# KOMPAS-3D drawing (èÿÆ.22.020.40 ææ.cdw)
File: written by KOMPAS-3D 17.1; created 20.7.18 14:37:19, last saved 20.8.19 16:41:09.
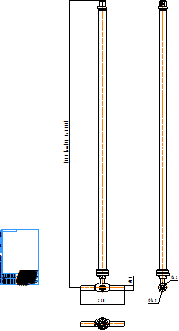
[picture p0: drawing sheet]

Sheet 1: A4, portrait

Title block, sheet 1: name: КШТ.22.020.40 С/С; sheets: 1; sheet format: A4; stored path: C:\Users\kka\KOMPAS_Work\Модели кранов для исследований\DN32\С удлинением\КШТ.22.032.40 СС.cdw

Referenced files in C:\Users\kka\KOMPAS_Work\Модели кранов для исследований\DN20\: АПТА.0203-1057.04.01 _ Корпус крана Ду20.m3d, АПТА.0203-2607.00.01 _ Шар Ду20.m3d, АПТА.0203-2607.02.02 _ Кольцо горловое Ду20.m3d, АПТА.0203-2607.02.03 _ Пружина тарельчатая Ду20.m3d, АПТА.0203-2607.02.04 _ Кольцо опорное Ду20.m3d, АПТА.0203-2607.02.05 _ Уплотнение седловое Ду20.m3d, АПТА.0203-2607.04.03 _ Шток Ду20 исполнение 1.m3d, АПТА.0203-1018.04.02 _ Корпус штока Ду10-32.m3d, АПТА.0203-1018.04.04 _ Шайба фрикционная Ду10-32.m3d, АПТА.0203-1057.03.01 _ Патрубок сварной точенный Ду20 (труба по ГОСТ).m3d, АПТА.0203-1057.00.00 _ Кран шаровой сварной Ду20 (Труба по ГОСТ).a3d!АПТА.0203-1057.00.00!Деталь (локальная).m3d, АПТА.0203-1057.00.00 _ Кран шаровой сварной Ду20 (Труба по ГОСТ).a3d!АПТА.0203-1057.00.00!Деталь (локальная) 1.m3d, Кольцо Viton 10.3x2.4.m3d, Кольцо EPDM 10.3x2.4.m3d, АПТА.0203-1018.01.02 _ Подкладка для кольца Ду10-32.m3d, АПТА.0203-1018.01.01 _ Кольцо прокладочное Ду10-32.m3d, АПТА.0203-1057.00.00 _ Кран шаровой сварной Ду20 (Труба по ГОСТ).a3d
Referenced files in C:\Program Files\ASCON\KOMPAS-3D v17\Libs\PartLib\DATA\VAULT\methods\kompas\3d\: PLib_Pin_3128_712.m3d, PLib_Blind_Nut_type1_900.m3d, PLib_Bolt_1_900.m3d, PLib_Washer_2_712.m3d, PLib_Pins_GOST_14229_911.m3d, PLib_Screw_GOST_8878-84_900.m3d
Referenced files in C:\Users\kka\KOMPAS_Work\Модели кранов для исследований\DN32\: ручка15-32.m3d, АПТА.0203-1018.03.00 _ Ручка Ду10-32.a3d
Referenced files in C:\Users\kka\KOMPAS_Work\КШ удлиненные ПП МОСФЛОУЛАЙН ф. ADL\DN25ПП\: ухватка15-32.m3d
Referenced files in C:\Users\kka\KOMPAS_Work\Удлинения БИВАЛ ф. ADL\Небюджет\Специальные ISO фланцы\: Фланец Ду15-32.m3d
Referenced files in C:\Users\kka\KOMPAS_Work\Удлинения БИВАЛ ф. ADL\Небюджет\Удлинения_2010\УШДн15-32\: УШ.251.00.03 _ Фланец нижний.m3d, УШ.251.00.07 _ Прокладка Ду20-50.m3d, УШ.251.00.05 _ Шток удлинителя Ду20-50.m3d, УШ.251.00.04 _ Гайка 32.m3d, УШ.251.00.01 _ Крышка удлинения.m3d, УШ.251.00.06 _ Тело удлинителя Ду20-50.m3d, УШ.251.00.08 _ Адаптер Ду20-32.m3d, УШ.251.00.00 _ Удлинение штока Ду20-32.a3d!УШ.251.00.00!Деталь (локальная).m3d, АПТА.0203-2617.11.03 - Кольцо прокладочное Ду65-80.m3d, УШ.251.00.00 _ Удлинение штока Ду20-32.a3d!УШ.251.00.00!Деталь (локальная) 1.m3d, УШ.251.00.00 _ Удлинение штока Ду20-32.a3d
Referenced files in C:\Users\kka\KOMPAS_Work\Модели кранов для исследований\DN80\: Кольцо EPDM 19.2x3.m3d
Referenced files in C:\Users\kka\KOMPAS_Work\Модели кранов для исследований\DN20\С удлинением\: КШТ.22.020.40 СС.a3d
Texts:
  kka
  adl
  Рама для чертежей
  Лит-Масса-Масштаб
  Материал-Предприятие
  Масштаб
  Изм.
  Лист
  № докум.
  Подп.
  Дата
  Лит.
  Разраб.
  Пров.
  Т.контр.
  Листов
  Внимание! Данный продукт является объектом авторского права ООО «Торговый Дом АДЛ».
  Запрещается изменение, копирование, распространение
  (в том числе путем копирования на другие сайты и ресурсы в Интернете)
  или любое иное использование информации и объектов без предварительного
  согласия правообладателя (ООО «Торговый Дом АДЛ»).
  Н.контр.
  Утв.
  ООО "Торговый дом АДЛ"
  Изменение
  Номер документа
  Подпись
  Обозначение документа
  Наименование изделия
  Масса изделия по ГОСТ 2.109-73
  Порядковый номер листа
  Общее количество листов в документе
  Характер работы, выполненной лицом, подписавшим документ
  Наименование или индекс предприятия, выпускающего документ
  Инв. № подл.
  Подп. и дата
  Взам. инв. №
  Инв. № дубл.
  Инвентарный номер подлинника по ГОСТ 2.501-68
  Подпись принявшего подлинник в отдел технической документации
  Инвентарный номер подлинника, взамен которого выпущен данный подлинник
  Инвентарный номер дубликата по ГОСТ 2.502-68
  Подпись принявшего дубликат в отдел технической документации
  Справ. №
  Перв. примен.
  Обозначение документа, взамен или на основании которого выпущен данный документ
  Обозначение документа, в котором впервые записан данный документ
  Подпись лица, копировавшего чертеж
  Обозначение формата листа
  !Рама для чертежа
  Корпус крана Ду20
  АПТА.0203-1057.04.01
  Шар Ду20
  АПТА.0203-2607.00.01
  Кольцо горловое Ду20
  АПТА.0203-2607.02.02
  Пружина тарельчатая Ду20
  АПТА.0203-2607.02.03
  Кольцо опорное Ду20
  АПТА.0203-2607.02.04
  Уплотнение седловое Ду20
  АПТА.0203-2607.02.05
  Шток Ду20 исполнение 1
  АПТА.0203-2607.04.03
  Корпус штока Ду10-32
  АПТА.0203-1018.04.02
  Шайба фрикционная Ду10-32
  АПТА.0203-1018.04.04
  Патрубок сварной точенный Ду20 (труба по ГОСТ)
  АПТА.0203-1057.03.01
  Деталь (локальная)
  Кольцо Viton 10.3x2.4
  Кольцо EPDM 10.3x2.4
  Подкладка для кольца Ду10-32
  АПТА.0203-1018.01.02
  Кольцо прокладочное Ду10-32
  АПТА.0203-1018.01.01
  Штифт 2.3x24 ГОСТ 3128-70
  ручка15-32
  ухватка15-32
  Ручка Ду10-32
  АПТА.0203-1018.03.00
  Гайка М10-6H ГОСТ 11860-85
  Присоединительный ISO фланец Ду15-32
  ФС.1532.00.01
  Кран шаровой сварной Ду20 (Труба по ГОСТ)
  АПТА.0203-1057.00.00
  Фланец нижний
  УШ.251.00.03
  Прокладка Ду20-50
  УШ.251.00.07
  Шток удлинителя Ду20-50
  УШ.251.00.05
  Гайка 32
  УШ.251.00.04
  Крышка корпуса Ду15-32
  УШ.251.00.01
  Тело удлинителя Ду20-50
  УШ.251.00.06
  Адаптер Ду20-32
  УШ.251.00.08
  Корпус
  Болт М6-6gx25 ГОСТ 7805-70
  Шайба 6 65Г 019 ГОСТ 6402-70
  Штифт A.8x12 ГОСТ 14229-93
  Штифт A.8x30 ГОСТ 14229-93
  Кольцо прокладочное Ду65-80
  АПТА.0203-2617.11.03
  Кольцо EPDM 19.2x3
  Винт М4-6gx6.14H.019 ГОСТ 8878-93
  Удлинение штока Ду20-32
  УШ.251.00.00
Dimensions and other numbers on the sheet: 1:1; 1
